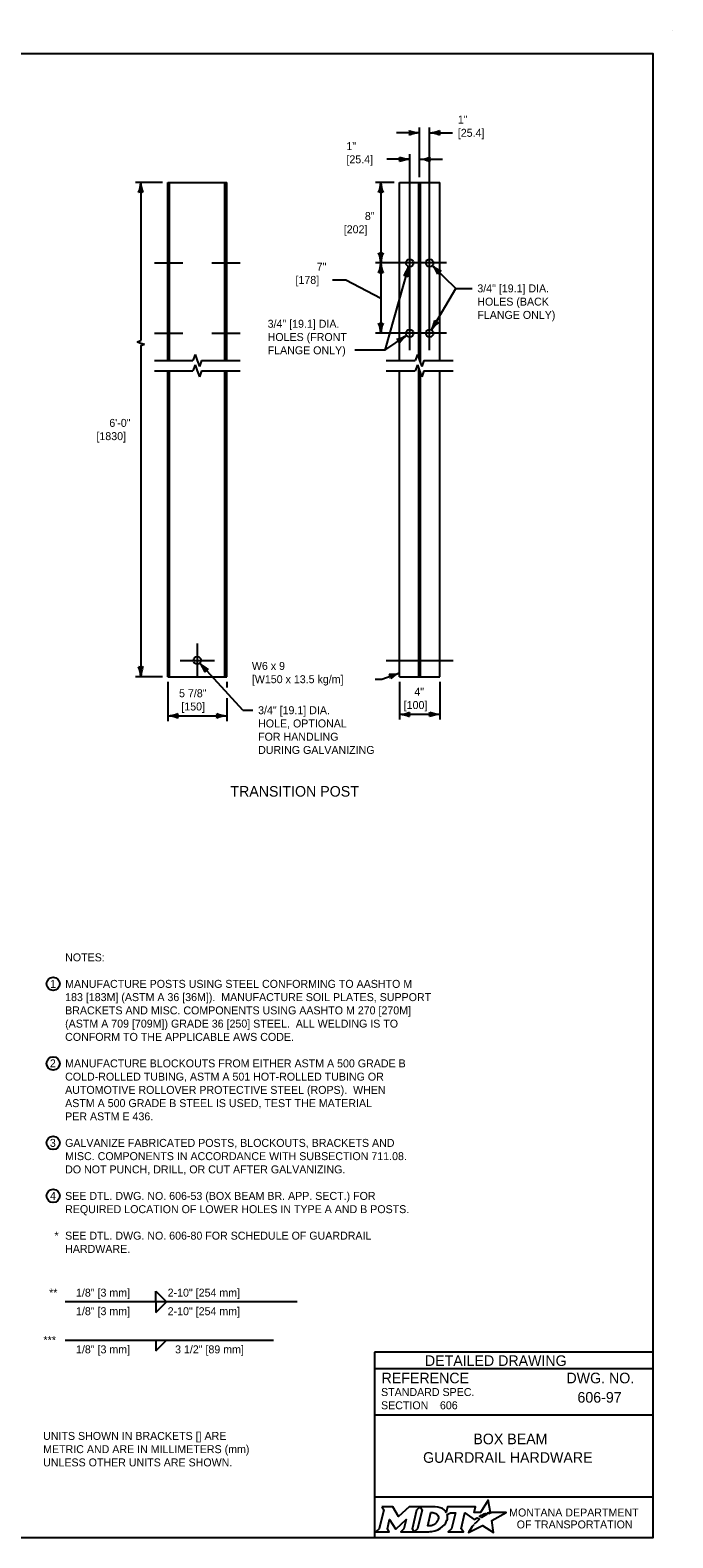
# Model space of a CAD drawing. Extents: x 49991.4 to 50021, y 49987.6 to 50011.4.
# Drawn here: x 50012.05 to 50016.9, y 49987.8 to 49999.18 of the extents above; entities that cross this region are included whole.
import ezdxf

# ---------------------------------------------------------------- set-up
doc = ezdxf.new("R2010")
doc.units = 0
for name, color, linetype in [('Default', 7, 'Continuous'), ('Level 1', 7, 'Continuous'), ('Level 2', 7, 'Continuous'), ('Level 3', 7, 'Continuous'), ('Level 4', 7, 'Continuous'), ('Level 5', 7, 'Continuous'), ('Level 6', 7, 'Continuous')]:
    doc.layers.add(name, color=color, linetype=linetype)

msp = doc.modelspace()

# ---------------------------------------------------------------- linework, layer by layer
at = {"layer": 'Default'}
for points in [[(50015.513, 49987.981), (50015.502, 49987.987), (50015.514, 49987.99), (50015.526, 49987.991), (50015.508, 49988.082), (50015.449, 49987.99), (50015.401, 49987.99), (50015.412, 49988.034), (50015.202, 49988.034), (50015.192, 49987.991), (50015.186, 49988)], [(50014.706, 49988.034), (50014.72, 49988.01), (50014.686, 49987.867), (50014.66, 49987.845), (50014.762, 49987.845), (50014.749, 49987.867), (50014.765, 49987.937), (50014.809, 49987.868), (50014.814, 49987.868), (50014.889, 49987.938), (50014.872, 49987.867), (50014.848, 49987.845), (50014.949, 49987.845), (50014.936, 49987.868), (50014.969, 49988.011)], [(50014.969, 49988.011), (50014.994, 49988.034), (50014.912, 49988.034), (50014.832, 49987.961), (50014.788, 49988.034), (50014.706, 49988.034)], [(50015.108, 49988.034), (50014.994, 49988.034), (50015.009, 49988.011), (50014.975, 49987.867), (50014.949, 49987.845), (50015.06, 49987.845)], [(50015.132, 49987.947), (50015.13, 49987.939), (50015.127, 49987.93), (50015.123, 49987.922), (50015.118, 49987.914), (50015.111, 49987.907), (50015.103, 49987.901), (50015.095, 49987.896), (50015.086, 49987.892), (50015.077, 49987.89), (50015.067, 49987.889), (50015.052, 49987.889), (50015.075, 49987.989), (50015.091, 49987.989), (50015.099, 49987.988), (50015.106, 49987.986), (50015.113, 49987.983), (50015.119, 49987.979), (50015.124, 49987.974), (50015.128, 49987.968), (50015.13, 49987.962), (50015.132, 49987.955), (50015.132, 49987.952), (50015.132, 49987.947)], [(50015.199, 49987.975), (50015.224, 49987.988), (50015.261, 49987.988), (50015.232, 49987.867), (50015.205, 49987.845), (50015.321, 49987.845), (50015.304, 49987.867), (50015.332, 49987.988), (50015.403, 49987.936), (50015.424, 49987.951), (50015.444, 49987.94)], [(50015.388, 49987.884), (50015.373, 49987.86), (50015.368, 49987.852), (50015.362, 49987.844), (50015.36, 49987.839), (50015.465, 49987.893), (50015.549, 49987.838), (50015.536, 49987.93), (50015.643, 49987.989), (50015.594, 49987.989), (50015.564, 49987.99), (50015.543, 49987.99), (50015.536, 49987.989), (50015.531, 49987.987), (50015.523, 49987.985), (50015.513, 49987.981)], [(50015.462, 49987.954), (50015.46, 49987.952), (50015.442, 49987.961), (50015.452, 49987.967), (50015.456, 49987.969), (50015.465, 49987.973), (50015.47, 49987.976), (50015.478, 49987.979), (50015.485, 49987.982), (50015.497, 49987.974), (50015.493, 49987.972), (50015.489, 49987.97), (50015.484, 49987.967), (50015.479, 49987.965), (50015.478, 49987.963), (50015.475, 49987.962), (50015.472, 49987.96), (50015.47, 49987.959), (50015.467, 49987.957), (50015.465, 49987.955), (50015.462, 49987.954)], [(50015.106, 49987.852), (50015.114, 49987.855), (50015.127, 49987.86), (50015.148, 49987.871)], [(50015.402, 49987.9), (50015.402, 49987.9)]]:
    msp.add_lwpolyline(points, dxfattribs=at)
for centre, radius, start, end in [((50015.087, 49987.973), 0.118, 300.9103, 339.1383), ((50015.131, 49987.955), 0.0709, 339.5329, 15.8582)]:
    msp.add_arc(centre, radius, start, end, dxfattribs=at)
for centre, major_axis, ratio, start_param, end_param in [((50015.106, 49987.986), (0.0834, -0.0037), 0.568097, 0.61298, 1.570796), ((50015.161, 49987.994), (0.0361, -0.0295), 0.469099, 1.225588, 1.570796), ((50015.433, 49987.93), (-0.0112, -0.0097), 0.021651, 3.157348, 6.283185), ((50015.06, 49987.993), (0, 0.148), 0.987302, 3.139398, 3.456847), ((50015.395, 49987.892), (-0.00694, -0.00806), 0.008222, 0, 3.137361), ((50015.412, 49987.911), (-0.0098, -0.0102), 0.016458, 3.141593, 6.279097)]:
    msp.add_ellipse(centre, major_axis=major_axis, ratio=ratio, start_param=start_param, end_param=end_param, dxfattribs=at)
at = {"layer": 'Level 1'}
for p, q in [((50016.9, 49999.176), (50016.9, 49999.176)), ((50013.092, 49998.027), (50013.537, 49998.027)), ((50013.092, 49996.682), (50013.092, 49998.027)), ((50013.106, 49996.682), (50013.106, 49998.027)), ((50013.523, 49996.682), (50013.523, 49998.027)), ((50013.537, 49996.682), (50013.537, 49998.027)), ((50014.839, 49998.027), (50015.143, 49998.027)), ((50014.839, 49996.682), (50014.839, 49998.027)), ((50015.143, 49996.682), (50015.143, 49998.027)), ((50013.092, 49994.297), (50013.092, 49996.606)), ((50013.106, 49994.297), (50013.106, 49996.606)), ((50013.523, 49994.297), (50013.523, 49996.606)), ((50013.537, 49994.297), (50013.537, 49996.606)), ((50014.839, 49994.297), (50014.839, 49996.606)), ((50015.143, 49994.297), (50015.143, 49996.606)), ((50013.092, 49994.297), (50013.537, 49994.297)), ((50014.839, 49994.297), (50015.143, 49994.297))]:
    msp.add_line(p, q, dxfattribs=at)
msp.add_lwpolyline([(49999.384, 49998.999), (50016.75, 49998.999), (50016.75, 49987.799), (49999.384, 49987.799)], close=True, dxfattribs=at)
for centre in [(50014.916, 49997.419), (50014.916, 49996.888), (50013.314, 49994.42)]:
    msp.add_circle(centre, 0.0285, dxfattribs=at)
at = {"layer": 'Level 2'}
for centre in [(50012.228, 49991.979), (50012.228, 49991.379), (50012.228, 49990.779), (50012.228, 49990.379)]:
    msp.add_circle(centre, 0.05, dxfattribs=at)
at = {"layer": 'Level 3'}
for p, q in [((50014.991, 49998.401), (50014.817, 49998.401)), ((50014.991, 49998.067), (50014.991, 49998.441)), ((50015.066, 49998.401), (50015.239, 49998.401)), ((50014.916, 49998.201), (50014.743, 49998.201)), ((50014.991, 49998.201), (50015.164, 49998.201)), ((50013.052, 49998.027), (50012.848, 49998.027)), ((50012.888, 49998.027), (50012.888, 49996.834)), ((50014.799, 49998.027), (50014.659, 49998.027)), ((50014.699, 49998.027), (50014.699, 49997.419)), ((50014.699, 49997.419), (50014.699, 49996.888)), ((50015.086, 49997.4), (50015.265, 49997.227)), ((50015.08, 49996.913), (50015.265, 49997.227)), ((50015.265, 49997.227), (50015.386, 49997.227)), ((50012.861, 49996.824), (50012.888, 49996.834)), ((50012.861, 49996.824), (50012.888, 49996.814)), ((50012.888, 49996.814), (50012.916, 49996.805)), ((50012.888, 49996.795), (50012.916, 49996.805)), ((50014.728, 49996.76), (50014.893, 49996.872)), ((50012.888, 49996.795), (50012.888, 49994.297)), ((50014.728, 49996.76), (50014.502, 49996.76)), ((50013.052, 49994.297), (50012.848, 49994.297)), ((50013.659, 49994.044), (50013.334, 49994.399)), ((50014.705, 49994.278), (50014.839, 49994.325)), ((50013.092, 49994.257), (50013.092, 49993.962)), ((50013.537, 49994.257), (50013.537, 49994.216)), ((50014.656, 49994.278), (50014.705, 49994.278)), ((50014.839, 49994.257), (50014.839, 49993.973)), ((50015.143, 49994.257), (50015.143, 49993.973)), ((50013.537, 49994.136), (50013.537, 49993.962)), ((50013.092, 49994.002), (50013.537, 49994.002)), ((50013.659, 49994.044), (50013.733, 49994.044)), ((50014.839, 49994.013), (50015.143, 49994.013)), ((50013.002, 49989.659), (50013.082, 49989.579)), ((50013.002, 49989.579), (50013.002, 49989.659)), ((50014.068, 49989.579), (50012.318, 49989.579)), ((50013.002, 49989.499), (50013.082, 49989.579)), ((50013.002, 49989.579), (50013.002, 49989.499)), ((50012.318, 49989.291), (50013.89, 49989.291)), ((50013.002, 49989.211), (50013.082, 49989.291)), ((50013.002, 49989.291), (50013.002, 49989.211))]:
    msp.add_line(p, q, dxfattribs=at)
for points in [[(50014.908, 49997.392), (50014.728, 49996.76)], [(50014.335, 49997.291), (50014.435, 49997.291), (50014.699, 49997.154)]]:
    msp.add_lwpolyline(points, dxfattribs=at)
for centre, radius, start, end in [((50014.863, 49998.401), 0.0548, 342.1388, 17.8612), ((50015.002, 49998.633), 0.233, 247.9228, 267.1727), ((50015, 49998.179), 0.222, 92.3605, 112.544), ((50015.056, 49998.623), 0.222, 272.3605, 292.544), ((50015.054, 49998.168), 0.233, 67.9228, 87.1727), ((50015.194, 49998.401), 0.0548, 162.1388, 197.8612), ((50014.925, 49998.423), 0.222, 247.456, 267.6395), ((50014.788, 49998.201), 0.0548, 342.1388, 17.8612), ((50014.928, 49997.968), 0.233, 92.8273, 112.0772), ((50014.979, 49998.433), 0.233, 272.8273, 292.0772), ((50014.982, 49997.979), 0.222, 67.456, 87.6395), ((50015.119, 49998.201), 0.0548, 162.1388, 197.8612), ((50012.656, 49998.038), 0.233, 337.9228, 357.1727), ((50012.888, 49997.898), 0.0548, 72.1388, 107.8612), ((50013.11, 49998.036), 0.222, 182.3605, 202.544), ((50014.477, 49998.036), 0.222, 337.456, 357.6395), ((50014.699, 49997.898), 0.0548, 72.1388, 107.8612), ((50014.932, 49998.038), 0.233, 182.8273, 202.0772), ((50014.699, 49997.548), 0.0548, 252.1388, 287.8612), ((50014.466, 49997.408), 0.233, 2.8273, 22.0772), ((50014.921, 49997.41), 0.222, 157.456, 177.6395), ((50014.477, 49997.429), 0.222, 337.456, 357.6395), ((50014.932, 49997.431), 0.233, 182.8273, 202.0772), ((50014.697, 49997.462), 0.222, 321.492, 341.6755), ((50015.135, 49997.339), 0.233, 166.8633, 186.1131), ((50014.925, 49997.246), 0.222, 23.5725, 43.756), ((50015.239, 49997.575), 0.233, 228.9438, 248.1937), ((50014.699, 49997.291), 0.0548, 72.1388, 107.8612), ((50014.873, 49997.269), 0.0548, 56.1748, 91.8971), ((50015.178, 49997.311), 0.0548, 118.2553, 153.9777), ((50014.699, 49997.016), 0.0548, 252.1388, 287.8612), ((50014.466, 49996.877), 0.233, 2.8273, 22.0772), ((50014.921, 49996.879), 0.222, 157.456, 177.6395), ((50014.874, 49997.021), 0.233, 332.3499, 351.5997), ((50015.267, 49996.792), 0.222, 126.9786, 147.1621), ((50015.145, 49997.023), 0.0548, 221.6614, 257.3838), ((50014.775, 49997.061), 0.222, 281.6639, 301.8474), ((50014.787, 49996.8), 0.0548, 16.3467, 52.0691), ((50015.033, 49996.686), 0.233, 127.0352, 146.2851), ((50012.666, 49994.287), 0.222, 2.3605, 22.544), ((50012.888, 49994.425), 0.0548, 252.1388, 287.8612), ((50013.121, 49994.285), 0.233, 157.9228, 177.1727), ((50013.164, 49994.255), 0.222, 19.974, 40.1575), ((50013.497, 49994.564), 0.233, 225.3453, 244.5951), ((50013.42, 49994.304), 0.0548, 114.6568, 150.3791), ((50014.774, 49994.537), 0.222, 266.7153, 286.8988), ((50014.718, 49994.282), 0.0548, 1.3981, 37.1205), ((50014.927, 49994.109), 0.233, 112.0866, 131.3364), ((50013.08, 49994.234), 0.233, 272.8273, 292.0772), ((50013.082, 49993.78), 0.222, 67.456, 87.6395), ((50013.22, 49994.002), 0.0548, 162.1388, 197.8612), ((50013.547, 49994.224), 0.222, 247.456, 267.6395), ((50013.409, 49994.002), 0.0548, 342.1388, 17.8612), ((50013.549, 49993.769), 0.233, 92.8273, 112.0772), ((50014.828, 49994.245), 0.233, 272.8273, 292.0772), ((50014.83, 49993.79), 0.222, 67.456, 87.6395), ((50014.967, 49994.013), 0.0548, 162.1388, 197.8612), ((50015.152, 49994.235), 0.222, 247.456, 267.6395), ((50015.014, 49994.013), 0.0548, 342.1388, 17.8612), ((50015.154, 49993.78), 0.233, 92.8273, 112.0772)]:
    msp.add_arc(centre, radius, start, end, dxfattribs=at)
at = {"layer": 'Level 4'}
for p, q in [((50014.984, 49996.703), (50014.984, 49998.027)), ((50014.998, 49996.662), (50014.998, 49998.027)), ((50013.092, 49997.448), (50013.106, 49997.448)), ((50013.092, 49997.391), (50013.106, 49997.391)), ((50013.523, 49997.448), (50013.537, 49997.448)), ((50013.523, 49997.391), (50013.537, 49997.391)), ((50013.092, 49996.917), (50013.106, 49996.917)), ((50013.523, 49996.917), (50013.537, 49996.917)), ((50013.092, 49996.86), (50013.106, 49996.86)), ((50013.523, 49996.86), (50013.537, 49996.86)), ((50014.984, 49994.297), (50014.984, 49996.626)), ((50014.998, 49994.297), (50014.998, 49996.586)), ((50014.984, 49994.448), (50014.998, 49994.448)), ((50014.984, 49994.391), (50014.998, 49994.391))]:
    msp.add_line(p, q, dxfattribs=at)
for centre in [(50015.066, 49997.419), (50015.066, 49996.888)]:
    msp.add_circle(centre, 0.0285, dxfattribs=at)
at = {"layer": 'Level 5'}
for p, q in [((50015.066, 49996.76), (50015.066, 49998.441)), ((50014.916, 49996.76), (50014.916, 49998.241)), ((50012.992, 49997.419), (50013.206, 49997.419)), ((50013.423, 49997.419), (50013.637, 49997.419)), ((50015.194, 49997.419), (50014.659, 49997.419)), ((50012.992, 49996.888), (50013.206, 49996.888)), ((50013.423, 49996.888), (50013.637, 49996.888)), ((50015.194, 49996.888), (50014.659, 49996.888)), ((50013.314, 49994.548), (50013.314, 49994.291)), ((50013.186, 49994.42), (50013.443, 49994.42)), ((50014.739, 49994.42), (50015.243, 49994.42)), ((50016.75, 49989.199), (50014.65, 49989.199)), ((50014.65, 49989.199), (50014.65, 49987.799)), ((50016.75, 49989.074), (50014.65, 49989.074)), ((50016.386, 49988.859), (50016.386, 49988.859)), ((50016.75, 49988.724), (50014.65, 49988.724)), ((50015.144, 49988.799), (50015.144, 49988.799)), ((50015.7, 49988.475), (50015.7, 49988.475)), ((50016.75, 49988.106), (50014.65, 49988.106))]:
    msp.add_line(p, q, dxfattribs=at)
at = {"layer": 'Level 6'}
for p, q in [((50013.298, 49996.728), (50013.282, 49996.682)), ((50013.298, 49996.728), (50013.314, 49996.682)), ((50014.975, 49996.728), (50014.958, 49996.682)), ((50014.975, 49996.728), (50014.991, 49996.682)), ((50012.992, 49996.682), (50013.282, 49996.682)), ((50012.992, 49996.606), (50013.282, 49996.606)), ((50013.298, 49996.651), (50013.282, 49996.606)), ((50013.298, 49996.651), (50013.314, 49996.606)), ((50013.314, 49996.682), (50013.331, 49996.637)), ((50013.314, 49996.606), (50013.331, 49996.56)), ((50013.347, 49996.682), (50013.331, 49996.637)), ((50013.347, 49996.606), (50013.331, 49996.56)), ((50013.347, 49996.682), (50013.637, 49996.682)), ((50013.347, 49996.606), (50013.637, 49996.606)), ((50014.739, 49996.682), (50014.958, 49996.682)), ((50014.739, 49996.606), (50014.958, 49996.606)), ((50014.975, 49996.651), (50014.958, 49996.606)), ((50014.975, 49996.651), (50014.991, 49996.606)), ((50014.991, 49996.682), (50015.007, 49996.637)), ((50014.991, 49996.606), (50015.007, 49996.56)), ((50015.023, 49996.682), (50015.007, 49996.637)), ((50015.023, 49996.606), (50015.007, 49996.56)), ((50015.023, 49996.682), (50015.243, 49996.682)), ((50015.023, 49996.606), (50015.243, 49996.606))]:
    msp.add_line(p, q, dxfattribs=at)

# ---------------------------------------------------------------- texts
at = {"layer": 'Default'}
for s, p in [('MONTANA DEPARTMENT', (50015.666, 49987.96)), ('OF TRANSPORTATION', (50015.723, 49987.87))]:
    msp.add_text(s, height=0.06, dxfattribs=at).set_placement(p)
at = {"layer": 'Level 2'}
for s, p in [('1"', (50015.279, 49998.471)), ('[25.4]', (50015.279, 49998.371)), ('1"', (50014.439, 49998.271)), ('[25.4]', (50014.439, 49998.171)), ('8"', (50014.578, 49997.743)), ('[202]', (50014.419, 49997.643)), ('7"', (50014.215, 49997.361)), ('[178]', (50014.055, 49997.261)), ('3/4" [19.1] DIA.', (50015.426, 49997.197)), ('HOLES (BACK', (50015.426, 49997.097)), ('FLANGE ONLY)', (50015.426, 49996.997)), ('3/4" [19.1] DIA.', (50013.845, 49996.93)), ('HOLES (FRONT', (50013.845, 49996.83)), ('FLANGE ONLY)', (50013.845, 49996.73)), ('6\'-0"', (50012.651, 49996.182)), ('[1830]', (50012.554, 49996.082)), ('5 7/8"', (50013.177, 49994.142)), ('4"', (50014.951, 49994.153)), ('[150]', (50013.194, 49994.042)), ('[100]', (50014.871, 49994.053))]:
    msp.add_text(s, height=0.06, rotation=360, dxfattribs=at).set_placement(p)
for s, height, p in [('W6 x 9', 0.06, (50013.726, 49994.348)), ('[W150 x 13.5 kg/m]', 0.06, (50013.726, 49994.248)), ('3/4" [19.1] DIA.', 0.06, (50013.773, 49994.014)), ('HOLE, OPTIONAL', 0.06, (50013.773, 49993.914)), ('FOR HANDLING', 0.06, (50013.773, 49993.814)), ('DURING GALVANIZING', 0.06, (50013.773, 49993.714)), ('TRANSITION POST', 0.08, (50013.564, 49993.392)), ('NOTES:', 0.06, (50012.318, 49992.149)), ('1', 0.06, (50012.205, 49991.949)), ('183 [183M] (ASTM A 36 [36M]).  MANUFACTURE SOIL PLATES, SUPPORT', 0.06, (50012.318, 49991.849)), ('MANUFACTURE POSTS USING STEEL CONFORMING TO AASHTO M', 0.06, (50012.318, 49991.949)), ('BRACKETS AND MISC. COMPONENTS USING AASHTO M 270 [270M]', 0.06, (50012.318, 49991.749)), ('(ASTM A 709 [709M]) GRADE 36 [250] STEEL.  ALL WELDING IS TO', 0.06, (50012.318, 49991.649)), ('CONFORM TO THE APPLICABLE AWS CODE.', 0.06, (50012.318, 49991.549)), ('2', 0.06, (50012.203, 49991.349)), ('MANUFACTURE BLOCKOUTS FROM EITHER ASTM A 500 GRADE B', 0.06, (50012.318, 49991.349)), ('COLD-ROLLED TUBING, ASTM A 501 HOT-ROLLED TUBING OR ', 0.06, (50012.318, 49991.249)), ('AUTOMOTIVE ROLLOVER PROTECTIVE STEEL (ROPS).  WHEN', 0.06, (50012.318, 49991.149)), ('ASTM A 500 GRADE B STEEL IS USED, TEST THE MATERIAL', 0.06, (50012.318, 49991.049)), ('PER ASTM E 436.', 0.06, (50012.318, 49990.949)), ('3', 0.06, (50012.203, 49990.749)), ('GALVANIZE FABRICATED POSTS, BLOCKOUTS, BRACKETS AND ', 0.06, (50012.318, 49990.749)), ('MISC. COMPONENTS IN ACCORDANCE WITH SUBSECTION 711.08.', 0.06, (50012.318, 49990.649)), ('DO NOT PUNCH, DRILL, OR CUT AFTER GALVANIZING.', 0.06, (50012.318, 49990.549)), ('4', 0.06, (50012.204, 49990.349)), ('SEE DTL. DWG. NO. 606-53 (BOX BEAM BR. APP. SECT.) FOR ', 0.06, (50012.318, 49990.349)), ('REQUIRED LOCATION OF LOWER HOLES IN TYPE A AND B POSTS.  ', 0.06, (50012.318, 49990.249)), ('*', 0.06, (50012.238, 49990.049)), ('SEE DTL. DWG. NO. 606-80 FOR SCHEDULE OF GUARDRAIL', 0.06, (50012.318, 49990.049)), ('HARDWARE.', 0.06, (50012.318, 49989.949)), ('**', 0.06, (50012.197, 49989.619)), ('1/8" [3 mm]', 0.06, (50012.4, 49989.619)), ('2-10" [254 mm]', 0.06, (50013.091, 49989.619)), ('1/8" [3 mm]', 0.06, (50012.4, 49989.479)), ('2-10" [254 mm]', 0.06, (50013.091, 49989.479)), ('***', 0.06, (50012.155, 49989.261)), ('1/8" [3 mm]', 0.06, (50012.4, 49989.191)), ('3 1/2" [89 mm]', 0.06, (50013.147, 49989.191)), ('606-97', 0.08, (50016.181, 49988.819)), ('606', 0.06, (50015.144, 49988.769)), ('UNITS SHOWN IN BRACKETS [] ARE ', 0.06, (50012.152, 49988.538)), ('METRIC AND ARE IN MILLIMETERS (mm) ', 0.06, (50012.152, 49988.438)), ('BOX BEAM', 0.08, (50015.396, 49988.505)), ('UNLESS OTHER UNITS ARE SHOWN.', 0.06, (50012.152, 49988.338)), ('GUARDRAIL HARDWARE', 0.08, (50015.017, 49988.365))]:
    msp.add_text(s, height=height, dxfattribs=at).set_placement(p)
at = {"layer": 'Level 5'}
for s, height, p in [('DETAILED DRAWING', 0.0799, (50015.031, 49989.096)), ('REFERENCE', 0.08, (50014.704, 49988.965)), ('DWG. NO.', 0.08, (50016.098, 49988.965)), ('STANDARD SPEC.', 0.06, (50014.7, 49988.869)), ('SECTION', 0.06, (50014.7, 49988.769))]:
    msp.add_text(s, height=height, dxfattribs=at).set_placement(p)

doc.saveas('drawing.dxf')
